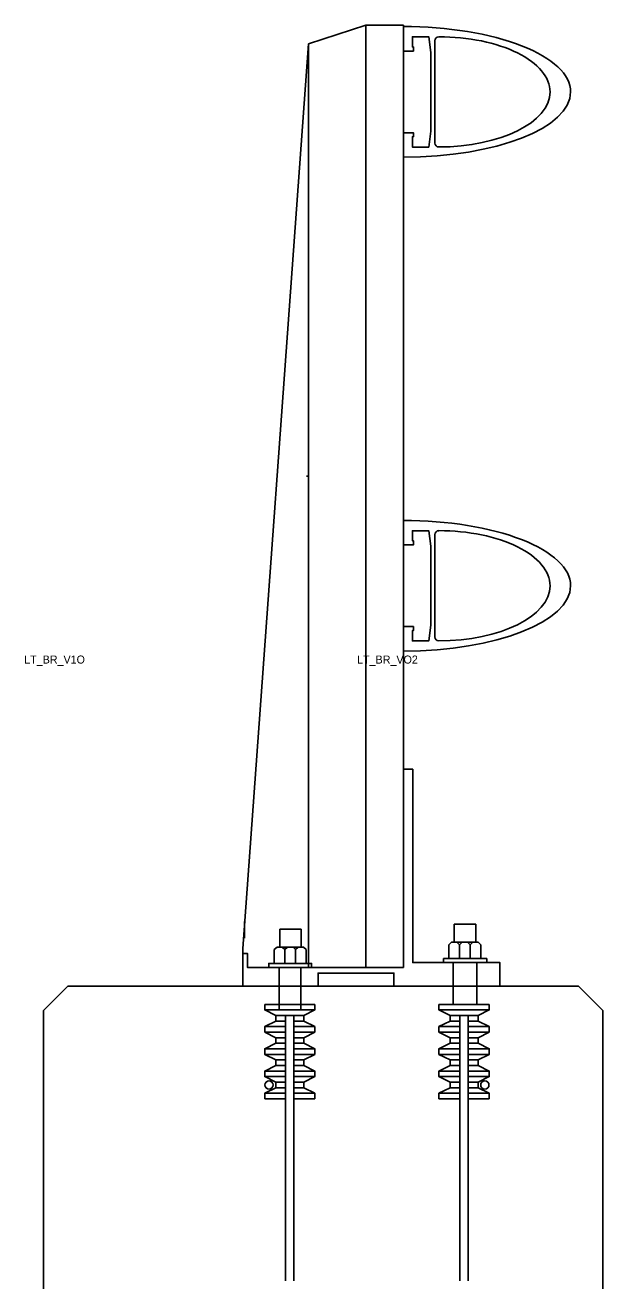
# Model space of a CAD drawing. Extents: x -26 to 4903, y -1010 to 9587.
# Drawn here: x 1109.895 to 1111.339, y 3545.515 to 3548.653 of the extents above; entities that cross this region are included whole.
import ezdxf

# ---------------------------------------------------------------- set-up
doc = ezdxf.new("R2010")
doc.units = 0
doc.layers.add('Default', color=7, linetype='Continuous')
doc.layers.add('Typical Bridge Rail Two Bar CELL', color=7, linetype='Continuous')

msp = doc.modelspace()

# ---------------------------------------------------------------- linework, layer by layer
at = {"layer": 'Default'}
for p, q in [((1110.6038, 3548.6064), (1110.7463, 3548.6528)), ((1110.8404, 3548.6528), (1110.7463, 3548.6528)), ((1110.7463, 3546.2985), (1110.7463, 3548.6528)), ((1110.8404, 3546.2985), (1110.8404, 3548.6528)), ((1110.6038, 3548.6064), (1110.4396, 3546.3454)), ((1110.6038, 3546.2985), (1110.6038, 3548.6064)), ((1110.9191, 3548.6139), (1110.9191, 3548.4859)), ((1110.9191, 3548.358), (1110.9191, 3548.4859)), ((1110.6038, 3547.5261), (1110.5987, 3547.5261)), ((1110.9191, 3547.3797), (1110.9191, 3547.2521)), ((1110.9191, 3547.1242), (1110.9191, 3547.2521)), ((1110.4439, 3546.3718), (1110.4439, 3546.4131)), ((1111.0211, 3546.406), (1110.9672, 3546.406)), ((1110.9672, 3546.406), (1110.9672, 3546.3615)), ((1111.0211, 3546.3615), (1111.0211, 3546.406)), ((1110.5849, 3546.3935), (1110.5314, 3546.3935)), ((1110.5314, 3546.3935), (1110.5314, 3546.3493)), ((1110.5849, 3546.3493), (1110.5849, 3546.3935)), ((1110.4396, 3546.2985), (1110.4396, 3546.3454)), ((1110.9644, 3546.206), (1110.9644, 3546.3103)), ((1111.0235, 3546.206), (1111.0235, 3546.3103)), ((1110.5302, 3546.1942), (1110.5302, 3546.2985)), ((1110.5845, 3546.1942), (1110.5845, 3546.2985)), ((1109.9412, 3546.1903), (1110.0022, 3546.2513)), ((1111.2778, 3546.2513), (1110.0022, 3546.2513)), ((1111.2778, 3546.2513), (1111.3388, 3546.1903)), ((1109.9412, 3546.1903), (1109.9412, 3543.2592)), ((1110.6191, 3546.206), (1110.4939, 3546.206)), ((1110.6191, 3546.1923), (1110.4939, 3546.1923)), ((1111.0545, 3546.206), (1110.9294, 3546.206)), ((1111.0545, 3546.1923), (1110.9294, 3546.1923)), ((1111.3388, 3546.1903), (1111.3388, 3543.2592)), ((1110.5459, 3546.1505), (1110.4939, 3546.1505)), ((1110.5459, 3546.1781), (1110.5215, 3546.1781)), ((1110.5459, 3546.1643), (1110.5215, 3546.1643)), ((1110.5668, 3546.1785), (1110.5459, 3546.1785)), ((1110.5459, 3546.1785), (1110.5459, 3545.5151)), ((1110.5668, 3546.1785), (1110.5668, 3545.5151)), ((1110.5912, 3546.1781), (1110.5668, 3546.1781)), ((1110.5912, 3546.1643), (1110.5668, 3546.1643)), ((1110.6191, 3546.1505), (1110.5668, 3546.1505)), ((1110.9817, 3546.1505), (1110.9294, 3546.1505)), ((1110.9817, 3546.1781), (1110.9573, 3546.1781)), ((1110.9817, 3546.1643), (1110.9573, 3546.1643)), ((1110.9817, 3546.1785), (1110.9817, 3545.5151)), ((1111.0026, 3546.1781), (1110.9817, 3546.1781)), ((1111.0026, 3546.1785), (1111.0026, 3545.5151)), ((1111.027, 3546.1781), (1111.0026, 3546.1781)), ((1111.027, 3546.1643), (1111.0026, 3546.1643)), ((1111.0545, 3546.1505), (1111.0026, 3546.1505)), ((1110.5459, 3546.1367), (1110.4939, 3546.1367)), ((1110.5459, 3546.1226), (1110.5215, 3546.1226)), ((1110.6191, 3546.1367), (1110.5668, 3546.1367)), ((1110.5912, 3546.1226), (1110.5668, 3546.1226)), ((1110.9817, 3546.1367), (1110.9294, 3546.1367)), ((1110.9817, 3546.1226), (1110.9573, 3546.1226)), ((1111.0545, 3546.1367), (1111.0026, 3546.1367)), ((1111.027, 3546.1226), (1111.0026, 3546.1226)), ((1110.5459, 3546.095), (1110.4939, 3546.095)), ((1110.5459, 3546.1088), (1110.5215, 3546.1088)), ((1110.5912, 3546.1088), (1110.5668, 3546.1088)), ((1110.6191, 3546.095), (1110.5668, 3546.095)), ((1110.9817, 3546.095), (1110.9294, 3546.095)), ((1110.9817, 3546.1088), (1110.9573, 3546.1088)), ((1111.027, 3546.1088), (1111.0026, 3546.1088)), ((1111.0545, 3546.095), (1111.0026, 3546.095)), ((1110.5459, 3546.0808), (1110.4939, 3546.0808)), ((1110.5459, 3546.0671), (1110.5215, 3546.0671)), ((1110.6191, 3546.0808), (1110.5668, 3546.0808)), ((1110.5912, 3546.0671), (1110.5668, 3546.0671)), ((1110.9817, 3546.0808), (1110.9294, 3546.0808)), ((1110.9817, 3546.0671), (1110.9573, 3546.0671)), ((1111.0545, 3546.0808), (1111.0026, 3546.0808)), ((1111.027, 3546.0671), (1111.0026, 3546.0671)), ((1110.5459, 3546.0395), (1110.4939, 3546.0395)), ((1110.5459, 3546.0257), (1110.4939, 3546.0257)), ((1110.5459, 3546.0533), (1110.5215, 3546.0533)), ((1110.5912, 3546.0533), (1110.5668, 3546.0533)), ((1110.6191, 3546.0395), (1110.5668, 3546.0395)), ((1110.6191, 3546.0257), (1110.5668, 3546.0257)), ((1110.9817, 3546.0395), (1110.9294, 3546.0395)), ((1110.9817, 3546.0257), (1110.9294, 3546.0257)), ((1110.9817, 3546.0533), (1110.9573, 3546.0533)), ((1111.027, 3546.0533), (1111.0026, 3546.0533)), ((1111.0545, 3546.0395), (1111.0026, 3546.0395)), ((1111.0545, 3546.0257), (1111.0026, 3546.0257)), ((1110.5459, 3546.0115), (1110.5215, 3546.0115)), ((1110.5459, 3545.9978), (1110.5215, 3545.9978)), ((1110.5912, 3546.0115), (1110.5668, 3546.0115)), ((1110.5912, 3545.9978), (1110.5668, 3545.9978)), ((1110.9817, 3546.0115), (1110.9573, 3546.0115)), ((1110.9817, 3545.9978), (1110.9573, 3545.9978)), ((1111.027, 3546.0115), (1111.0026, 3546.0115)), ((1111.027, 3545.9978), (1111.0026, 3545.9978)), ((1110.5459, 3545.984), (1110.4939, 3545.984)), ((1110.5459, 3545.9702), (1110.4939, 3545.9702)), ((1110.6191, 3545.984), (1110.5668, 3545.984)), ((1110.6191, 3545.9702), (1110.5668, 3545.9702)), ((1110.9817, 3545.984), (1110.9294, 3545.984)), ((1110.9817, 3545.9702), (1110.9294, 3545.9702)), ((1111.0545, 3545.984), (1111.0026, 3545.984)), ((1111.0545, 3545.9702), (1111.0026, 3545.9702))]:
    msp.add_line(p, q, dxfattribs=at)
for points in [[(1110.8404, 3548.323), (1110.8404, 3548.384), (1110.8656, 3548.384), (1110.8656, 3548.3737), (1110.8632, 3548.3737), (1110.8632, 3548.3482), (1110.9038, 3548.3482), (1110.9089, 3548.3875), (1110.9089, 3548.4859), (1110.9089, 3548.5843), (1110.9038, 3548.6237), (1110.8632, 3548.6237), (1110.8632, 3548.5982), (1110.8656, 3548.5982), (1110.8656, 3548.5879), (1110.8404, 3548.5879), (1110.8404, 3548.6493)], [(1110.8404, 3547.0887), (1110.8404, 3547.1501), (1110.8656, 3547.1501), (1110.8656, 3547.1399), (1110.8632, 3547.1399), (1110.8632, 3547.1143), (1110.9038, 3547.1143), (1110.9089, 3547.1537), (1110.9089, 3547.2521), (1110.9089, 3547.3505), (1110.9038, 3547.3895), (1110.8632, 3547.3895), (1110.8632, 3547.3643), (1110.8656, 3547.3643), (1110.8656, 3547.354), (1110.8404, 3547.354), (1110.8404, 3547.4151)], [(1111.0817, 3546.2513), (1111.0817, 3546.3103), (1110.864, 3546.3103), (1110.864, 3546.7934), (1110.8404, 3546.7934), (1110.8404, 3546.2985), (1110.4506, 3546.2985), (1110.4506, 3546.3332), (1110.4396, 3546.3332), (1110.4396, 3546.2513), (1110.6274, 3546.2513), (1110.6274, 3546.284), (1110.8168, 3546.284), (1110.8168, 3546.2513), (1111.0817, 3546.2513)], [(1110.5975, 3546.3084), (1110.5975, 3546.3427), (1110.5908, 3546.3493), (1110.525, 3546.3493), (1110.518, 3546.3427), (1110.518, 3546.3084), (1110.5975, 3546.3084), (1110.5711, 3546.3084), (1110.5711, 3546.3427), (1110.5778, 3546.3493), (1110.5711, 3546.3427), (1110.5648, 3546.3493), (1110.551, 3546.3493), (1110.5444, 3546.3427), (1110.5444, 3546.3084), (1110.5444, 3546.3427), (1110.5377, 3546.3493)], [(1111.0337, 3546.3202), (1111.0337, 3546.3545), (1111.0274, 3546.3612), (1110.9609, 3546.3612), (1110.9542, 3546.3545), (1110.9542, 3546.3202), (1111.0337, 3546.3202), (1111.0069, 3546.3202), (1111.0069, 3546.3545), (1111.014, 3546.3612), (1111.0069, 3546.3545), (1111.0006, 3546.3612), (1110.9869, 3546.3612), (1110.9805, 3546.3545), (1110.9805, 3546.3202), (1110.9805, 3546.3545), (1110.9742, 3546.3612)], [(1110.6112, 3546.2978), (1110.6112, 3546.3084), (1110.5577, 3546.3084), (1110.5042, 3546.3084), (1110.5042, 3546.2978)], [(1111.0487, 3546.31), (1111.0487, 3546.3206), (1110.9947, 3546.3206), (1110.9408, 3546.3206), (1110.9408, 3546.31)], [(1110.4939, 3546.206), (1110.4939, 3546.1923), (1110.5215, 3546.1781), (1110.5215, 3546.1643), (1110.4939, 3546.1505), (1110.4939, 3546.1367), (1110.5215, 3546.1226), (1110.5215, 3546.1088), (1110.4939, 3546.095), (1110.4939, 3546.0808), (1110.5215, 3546.0671), (1110.5215, 3546.0533), (1110.4939, 3546.0395), (1110.4939, 3546.0257), (1110.5215, 3546.0115), (1110.5215, 3545.9978), (1110.4939, 3545.984), (1110.4939, 3545.9702)], [(1110.6191, 3546.206), (1110.6191, 3546.1923), (1110.5916, 3546.1781), (1110.5916, 3546.1643), (1110.6191, 3546.1505), (1110.6191, 3546.1367), (1110.5916, 3546.1226), (1110.5916, 3546.1088), (1110.6191, 3546.095), (1110.6191, 3546.0808), (1110.5916, 3546.0671), (1110.5916, 3546.0533), (1110.6191, 3546.0395), (1110.6191, 3546.0257), (1110.5916, 3546.0115), (1110.5916, 3545.9978), (1110.6191, 3545.984), (1110.6191, 3545.9702)], [(1110.9294, 3546.206), (1110.9294, 3546.1923), (1110.9573, 3546.1781), (1110.9573, 3546.1643), (1110.9294, 3546.1505), (1110.9294, 3546.1367), (1110.9573, 3546.1226), (1110.9573, 3546.1088), (1110.9294, 3546.095), (1110.9294, 3546.0808), (1110.9573, 3546.0671), (1110.9573, 3546.0533), (1110.9294, 3546.0395), (1110.9294, 3546.0257), (1110.9573, 3546.0115), (1110.9573, 3545.9978), (1110.9294, 3545.984), (1110.9294, 3545.9702)], [(1111.055, 3546.206), (1111.055, 3546.1923), (1111.027, 3546.1781), (1111.027, 3546.1643), (1111.055, 3546.1505), (1111.055, 3546.1367), (1111.027, 3546.1226), (1111.027, 3546.1088), (1111.055, 3546.095), (1111.055, 3546.0808), (1111.027, 3546.0671), (1111.027, 3546.0533), (1111.055, 3546.0395), (1111.055, 3546.0257), (1111.027, 3546.0115), (1111.027, 3545.9978), (1111.055, 3545.984), (1111.055, 3545.9702)]]:
    msp.add_lwpolyline(points, dxfattribs=at)
for centre in [(1110.5048, 3546.0046), (1111.0439, 3546.0046)]:
    msp.add_circle(centre, 0.0104, dxfattribs=at)
for centre, start, end in [((1110.929, 3548.6138), 90, 180), ((1110.929, 3548.3581), 180, 270), ((1110.929, 3547.3798), 90, 180), ((1110.929, 3547.1241), 180, 270)]:
    msp.add_arc(centre, 0.00979, start, end, dxfattribs=at)
for centre, major_axis, ratio, start_param, end_param in [((1110.8402, 3548.486), (0.418, 0), 0.39036, 6.282787, 7.853967), ((1110.929, 3548.486), (0.2778, 0), 0.495501, 6.282718, 7.853881), ((1110.8402, 3548.486), (0.418, 0), 0.39036, 4.712404, 6.282787), ((1110.929, 3548.486), (0.2778, 0), 0.495501, 4.712489, 6.282718), ((1110.8402, 3547.252), (0.418, 0), 0.39036, 6.282787, 7.853967), ((1110.929, 3547.252), (0.2778, 0), 0.495501, 6.282718, 7.853881), ((1110.8402, 3547.252), (0.418, 0), 0.39036, 4.712404, 6.282787), ((1110.929, 3547.252), (0.2778, 0), 0.495501, 4.712489, 6.282718)]:
    msp.add_ellipse(centre, major_axis=major_axis, ratio=ratio, start_param=start_param, end_param=end_param, dxfattribs=at)
at = {"layer": 'Typical Bridge Rail Two Bar CELL'}
for p, q in [((1110.6038, 3548.6064), (1110.7463, 3548.6528)), ((1110.8404, 3548.6528), (1110.7463, 3548.6528)), ((1110.7463, 3546.2985), (1110.7463, 3548.6528)), ((1110.8404, 3546.2985), (1110.8404, 3548.6528)), ((1110.6038, 3548.6064), (1110.4396, 3546.3454)), ((1110.6038, 3546.2985), (1110.6038, 3548.6064)), ((1110.9191, 3548.6139), (1110.9191, 3548.4859)), ((1110.9191, 3548.358), (1110.9191, 3548.4859)), ((1110.6038, 3547.5261), (1110.5987, 3547.5261)), ((1110.9191, 3547.3797), (1110.9191, 3547.2521)), ((1110.9191, 3547.1242), (1110.9191, 3547.2521)), ((1110.4439, 3546.3718), (1110.4439, 3546.4131)), ((1111.0211, 3546.406), (1110.9672, 3546.406)), ((1110.9672, 3546.406), (1110.9672, 3546.3615)), ((1111.0211, 3546.3615), (1111.0211, 3546.406)), ((1110.5849, 3546.3935), (1110.5314, 3546.3935)), ((1110.5314, 3546.3935), (1110.5314, 3546.3493)), ((1110.5849, 3546.3493), (1110.5849, 3546.3935)), ((1110.4396, 3546.2985), (1110.4396, 3546.3454)), ((1110.9644, 3546.206), (1110.9644, 3546.3103)), ((1111.0235, 3546.206), (1111.0235, 3546.3103)), ((1110.5302, 3546.1942), (1110.5302, 3546.2985)), ((1110.5845, 3546.1942), (1110.5845, 3546.2985)), ((1109.9412, 3546.1903), (1110.0022, 3546.2513)), ((1111.2778, 3546.2513), (1110.0022, 3546.2513)), ((1111.2778, 3546.2513), (1111.3388, 3546.1903)), ((1109.9412, 3546.1903), (1109.9412, 3543.2592)), ((1110.6191, 3546.206), (1110.4939, 3546.206)), ((1110.6191, 3546.1923), (1110.4939, 3546.1923)), ((1111.0545, 3546.206), (1110.9294, 3546.206)), ((1111.0545, 3546.1923), (1110.9294, 3546.1923)), ((1111.3388, 3546.1903), (1111.3388, 3543.2592)), ((1110.5459, 3546.1505), (1110.4939, 3546.1505)), ((1110.5459, 3546.1781), (1110.5215, 3546.1781)), ((1110.5459, 3546.1643), (1110.5215, 3546.1643)), ((1110.5668, 3546.1785), (1110.5459, 3546.1785)), ((1110.5459, 3546.1785), (1110.5459, 3545.5151)), ((1110.5668, 3546.1785), (1110.5668, 3545.5151)), ((1110.5912, 3546.1781), (1110.5668, 3546.1781)), ((1110.5912, 3546.1643), (1110.5668, 3546.1643)), ((1110.6191, 3546.1505), (1110.5668, 3546.1505)), ((1110.9817, 3546.1505), (1110.9294, 3546.1505)), ((1110.9817, 3546.1781), (1110.9573, 3546.1781)), ((1110.9817, 3546.1643), (1110.9573, 3546.1643)), ((1110.9817, 3546.1785), (1110.9817, 3545.5151)), ((1111.0026, 3546.1781), (1110.9817, 3546.1781)), ((1111.0026, 3546.1785), (1111.0026, 3545.5151)), ((1111.027, 3546.1781), (1111.0026, 3546.1781)), ((1111.027, 3546.1643), (1111.0026, 3546.1643)), ((1111.0545, 3546.1505), (1111.0026, 3546.1505)), ((1110.5459, 3546.1367), (1110.4939, 3546.1367)), ((1110.5459, 3546.1226), (1110.5215, 3546.1226)), ((1110.6191, 3546.1367), (1110.5668, 3546.1367)), ((1110.5912, 3546.1226), (1110.5668, 3546.1226)), ((1110.9817, 3546.1367), (1110.9294, 3546.1367)), ((1110.9817, 3546.1226), (1110.9573, 3546.1226)), ((1111.0545, 3546.1367), (1111.0026, 3546.1367)), ((1111.027, 3546.1226), (1111.0026, 3546.1226)), ((1110.5459, 3546.095), (1110.4939, 3546.095)), ((1110.5459, 3546.1088), (1110.5215, 3546.1088)), ((1110.5912, 3546.1088), (1110.5668, 3546.1088)), ((1110.6191, 3546.095), (1110.5668, 3546.095)), ((1110.9817, 3546.095), (1110.9294, 3546.095)), ((1110.9817, 3546.1088), (1110.9573, 3546.1088)), ((1111.027, 3546.1088), (1111.0026, 3546.1088)), ((1111.0545, 3546.095), (1111.0026, 3546.095)), ((1110.5459, 3546.0808), (1110.4939, 3546.0808)), ((1110.5459, 3546.0671), (1110.5215, 3546.0671)), ((1110.6191, 3546.0808), (1110.5668, 3546.0808)), ((1110.5912, 3546.0671), (1110.5668, 3546.0671)), ((1110.9817, 3546.0808), (1110.9294, 3546.0808)), ((1110.9817, 3546.0671), (1110.9573, 3546.0671)), ((1111.0545, 3546.0808), (1111.0026, 3546.0808)), ((1111.027, 3546.0671), (1111.0026, 3546.0671)), ((1110.5459, 3546.0395), (1110.4939, 3546.0395)), ((1110.5459, 3546.0257), (1110.4939, 3546.0257)), ((1110.5459, 3546.0533), (1110.5215, 3546.0533)), ((1110.5912, 3546.0533), (1110.5668, 3546.0533)), ((1110.6191, 3546.0395), (1110.5668, 3546.0395)), ((1110.6191, 3546.0257), (1110.5668, 3546.0257)), ((1110.9817, 3546.0395), (1110.9294, 3546.0395)), ((1110.9817, 3546.0257), (1110.9294, 3546.0257)), ((1110.9817, 3546.0533), (1110.9573, 3546.0533)), ((1111.027, 3546.0533), (1111.0026, 3546.0533)), ((1111.0545, 3546.0395), (1111.0026, 3546.0395)), ((1111.0545, 3546.0257), (1111.0026, 3546.0257)), ((1110.5459, 3546.0115), (1110.5215, 3546.0115)), ((1110.5459, 3545.9978), (1110.5215, 3545.9978)), ((1110.5912, 3546.0115), (1110.5668, 3546.0115)), ((1110.5912, 3545.9978), (1110.5668, 3545.9978)), ((1110.9817, 3546.0115), (1110.9573, 3546.0115)), ((1110.9817, 3545.9978), (1110.9573, 3545.9978)), ((1111.027, 3546.0115), (1111.0026, 3546.0115)), ((1111.027, 3545.9978), (1111.0026, 3545.9978)), ((1110.5459, 3545.984), (1110.4939, 3545.984)), ((1110.5459, 3545.9702), (1110.4939, 3545.9702)), ((1110.6191, 3545.984), (1110.5668, 3545.984)), ((1110.6191, 3545.9702), (1110.5668, 3545.9702)), ((1110.9817, 3545.984), (1110.9294, 3545.984)), ((1110.9817, 3545.9702), (1110.9294, 3545.9702)), ((1111.0545, 3545.984), (1111.0026, 3545.984)), ((1111.0545, 3545.9702), (1111.0026, 3545.9702))]:
    msp.add_line(p, q, dxfattribs=at)
for points in [[(1110.8404, 3548.323), (1110.8404, 3548.384), (1110.8656, 3548.384), (1110.8656, 3548.3737), (1110.8632, 3548.3737), (1110.8632, 3548.3482), (1110.9038, 3548.3482), (1110.9089, 3548.3875), (1110.9089, 3548.4859), (1110.9089, 3548.5843), (1110.9038, 3548.6237), (1110.8632, 3548.6237), (1110.8632, 3548.5982), (1110.8656, 3548.5982), (1110.8656, 3548.5879), (1110.8404, 3548.5879), (1110.8404, 3548.6493)], [(1110.8404, 3547.0887), (1110.8404, 3547.1501), (1110.8656, 3547.1501), (1110.8656, 3547.1399), (1110.8632, 3547.1399), (1110.8632, 3547.1143), (1110.9038, 3547.1143), (1110.9089, 3547.1537), (1110.9089, 3547.2521), (1110.9089, 3547.3505), (1110.9038, 3547.3895), (1110.8632, 3547.3895), (1110.8632, 3547.3643), (1110.8656, 3547.3643), (1110.8656, 3547.354), (1110.8404, 3547.354), (1110.8404, 3547.4151)], [(1111.0817, 3546.2513), (1111.0817, 3546.3103), (1110.864, 3546.3103), (1110.864, 3546.7934), (1110.8404, 3546.7934), (1110.8404, 3546.2985), (1110.4506, 3546.2985), (1110.4506, 3546.3332), (1110.4396, 3546.3332), (1110.4396, 3546.2513), (1110.6274, 3546.2513), (1110.6274, 3546.284), (1110.8168, 3546.284), (1110.8168, 3546.2513), (1111.0817, 3546.2513)], [(1110.5975, 3546.3084), (1110.5975, 3546.3427), (1110.5908, 3546.3493), (1110.525, 3546.3493), (1110.518, 3546.3427), (1110.518, 3546.3084), (1110.5975, 3546.3084), (1110.5711, 3546.3084), (1110.5711, 3546.3427), (1110.5778, 3546.3493), (1110.5711, 3546.3427), (1110.5648, 3546.3493), (1110.551, 3546.3493), (1110.5444, 3546.3427), (1110.5444, 3546.3084), (1110.5444, 3546.3427), (1110.5377, 3546.3493)], [(1111.0337, 3546.3202), (1111.0337, 3546.3545), (1111.0274, 3546.3612), (1110.9609, 3546.3612), (1110.9542, 3546.3545), (1110.9542, 3546.3202), (1111.0337, 3546.3202), (1111.0069, 3546.3202), (1111.0069, 3546.3545), (1111.014, 3546.3612), (1111.0069, 3546.3545), (1111.0006, 3546.3612), (1110.9869, 3546.3612), (1110.9805, 3546.3545), (1110.9805, 3546.3202), (1110.9805, 3546.3545), (1110.9742, 3546.3612)], [(1110.6112, 3546.2978), (1110.6112, 3546.3084), (1110.5577, 3546.3084), (1110.5042, 3546.3084), (1110.5042, 3546.2978)], [(1111.0487, 3546.31), (1111.0487, 3546.3206), (1110.9947, 3546.3206), (1110.9408, 3546.3206), (1110.9408, 3546.31)], [(1110.4939, 3546.206), (1110.4939, 3546.1923), (1110.5215, 3546.1781), (1110.5215, 3546.1643), (1110.4939, 3546.1505), (1110.4939, 3546.1367), (1110.5215, 3546.1226), (1110.5215, 3546.1088), (1110.4939, 3546.095), (1110.4939, 3546.0808), (1110.5215, 3546.0671), (1110.5215, 3546.0533), (1110.4939, 3546.0395), (1110.4939, 3546.0257), (1110.5215, 3546.0115), (1110.5215, 3545.9978), (1110.4939, 3545.984), (1110.4939, 3545.9702)], [(1110.6191, 3546.206), (1110.6191, 3546.1923), (1110.5916, 3546.1781), (1110.5916, 3546.1643), (1110.6191, 3546.1505), (1110.6191, 3546.1367), (1110.5916, 3546.1226), (1110.5916, 3546.1088), (1110.6191, 3546.095), (1110.6191, 3546.0808), (1110.5916, 3546.0671), (1110.5916, 3546.0533), (1110.6191, 3546.0395), (1110.6191, 3546.0257), (1110.5916, 3546.0115), (1110.5916, 3545.9978), (1110.6191, 3545.984), (1110.6191, 3545.9702)], [(1110.9294, 3546.206), (1110.9294, 3546.1923), (1110.9573, 3546.1781), (1110.9573, 3546.1643), (1110.9294, 3546.1505), (1110.9294, 3546.1367), (1110.9573, 3546.1226), (1110.9573, 3546.1088), (1110.9294, 3546.095), (1110.9294, 3546.0808), (1110.9573, 3546.0671), (1110.9573, 3546.0533), (1110.9294, 3546.0395), (1110.9294, 3546.0257), (1110.9573, 3546.0115), (1110.9573, 3545.9978), (1110.9294, 3545.984), (1110.9294, 3545.9702)], [(1111.055, 3546.206), (1111.055, 3546.1923), (1111.027, 3546.1781), (1111.027, 3546.1643), (1111.055, 3546.1505), (1111.055, 3546.1367), (1111.027, 3546.1226), (1111.027, 3546.1088), (1111.055, 3546.095), (1111.055, 3546.0808), (1111.027, 3546.0671), (1111.027, 3546.0533), (1111.055, 3546.0395), (1111.055, 3546.0257), (1111.027, 3546.0115), (1111.027, 3545.9978), (1111.055, 3545.984), (1111.055, 3545.9702)]]:
    msp.add_lwpolyline(points, dxfattribs=at)
for centre in [(1110.5048, 3546.0046), (1111.0439, 3546.0046)]:
    msp.add_circle(centre, 0.0104, dxfattribs=at)
for centre, start, end in [((1110.929, 3548.6138), 90, 180), ((1110.929, 3548.3581), 180, 270), ((1110.929, 3547.3798), 90, 180), ((1110.929, 3547.1241), 180, 270)]:
    msp.add_arc(centre, 0.00979, start, end, dxfattribs=at)
for centre, major_axis, ratio, start_param, end_param in [((1110.8402, 3548.486), (0.418, 0), 0.39036, 6.282787, 7.853967), ((1110.929, 3548.486), (0.2778, 0), 0.495501, 6.282718, 7.853881), ((1110.8402, 3548.486), (0.418, 0), 0.39036, 4.712404, 6.282787), ((1110.929, 3548.486), (0.2778, 0), 0.495501, 4.712489, 6.282718), ((1110.8402, 3547.252), (0.418, 0), 0.39036, 6.282787, 7.853967), ((1110.929, 3547.252), (0.2778, 0), 0.495501, 6.282718, 7.853881), ((1110.8402, 3547.252), (0.418, 0), 0.39036, 4.712404, 6.282787), ((1110.929, 3547.252), (0.2778, 0), 0.495501, 4.712489, 6.282718)]:
    msp.add_ellipse(centre, major_axis=major_axis, ratio=ratio, start_param=start_param, end_param=end_param, dxfattribs=at)

# ---------------------------------------------------------------- texts
at = {"layer": 'Default'}
for s, p in [('LT_BR_V1O', (1109.8933, 3547.0576)), ('LT_BR_VO2', (1110.7249, 3547.0576))]:
    msp.add_text(s, height=0.02, dxfattribs=at).set_placement(p)

doc.saveas('drawing.dxf')
